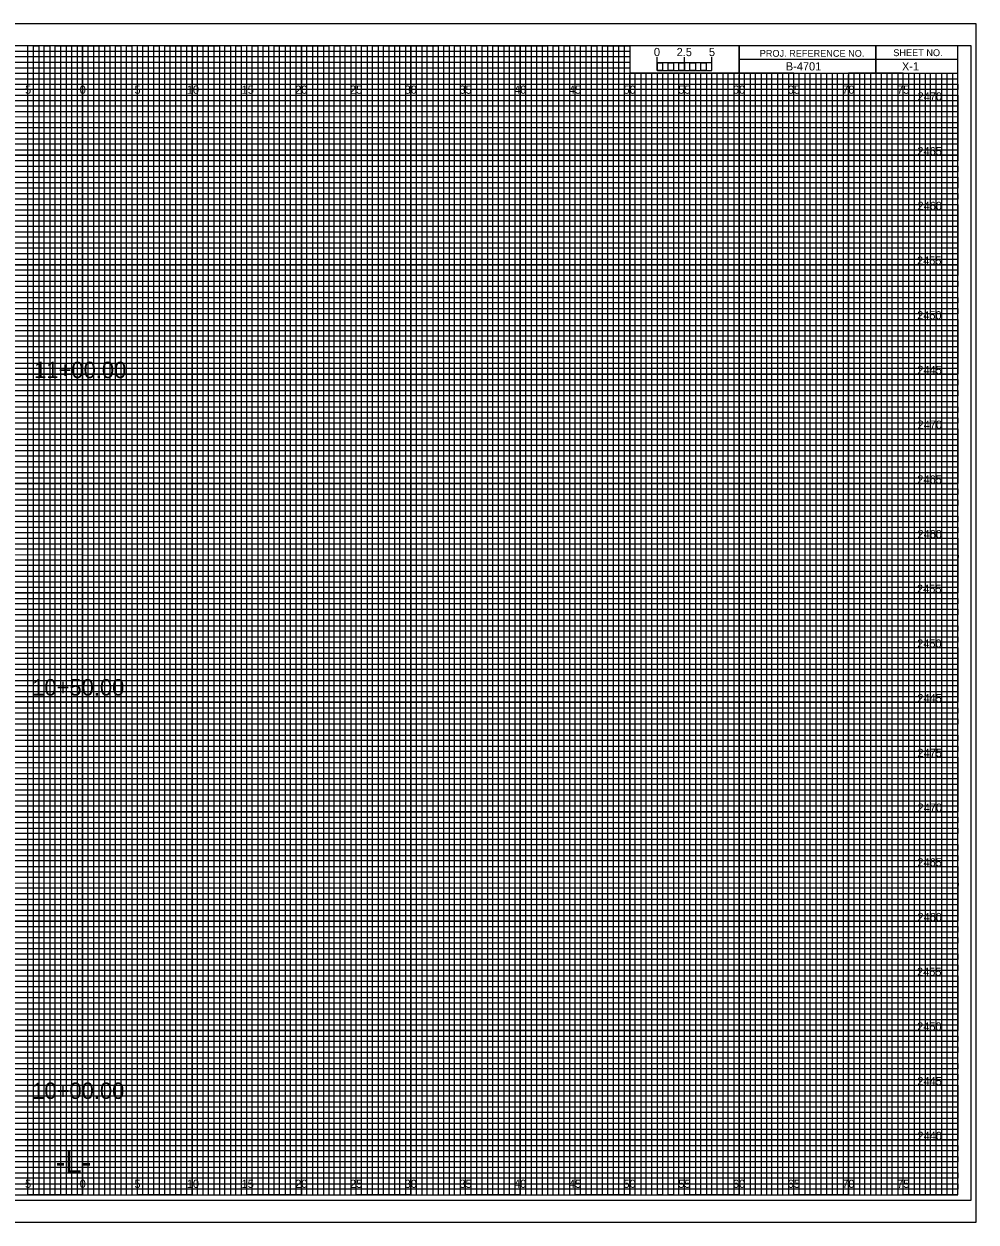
# Model space of a CAD drawing. Extents: x -7 to 162, y -2 to 107.
# Drawn here: x 74.6 to 161.7, y -2.5 to 107 of the extents above; entities that cross this region are included whole.
import ezdxf

# ---------------------------------------------------------------- set-up
doc = ezdxf.new("R2010")
doc.units = 0
for name, color, linetype in [('Exist CMT Pavement', 7, 'Continuous'), ('Exist Cross Section Cell', 7, 'Continuous'), ('Exist XS Ground Line', 7, 'Continuous'), ('Prop CMT Pvmt Course 1 Wedge', 7, 'Continuous'), ('Prop CMT Pvmt Surface', 7, 'Continuous'), ('Prop CMT Pvmt Surface Shoulder', 7, 'Continuous'), ('Prop CMT Pvmt Wedge Surface 1', 7, 'Continuous'), ('Prop CMT Pvmt Wedge Surface 2', 7, 'Continuous'), ('Prop CMT Pvmt Wedge Surface 3', 7, 'Continuous'), ('Prop CMT Shld Paved Course 1', 7, 'Continuous'), ('Prop CMT Shld Paved Course 2', 7, 'Continuous'), ('Prop CMT Shld Paved Course 3', 7, 'Continuous'), ('Prop CMT Slope Grass', 7, 'Continuous'), ('Prop CMT Subgrade Earthwork', 7, 'Continuous'), ('Prop XS EOT Tick Mark', 7, 'Continuous'), ('Scratch_Level_0', 7, 'Continuous'), ('Scratch_Level_1', 7, 'Continuous')]:
    doc.layers.add(name, color=color, linetype=linetype)

msp = doc.modelspace()

# ---------------------------------------------------------------- linework, layer by layer
at = {"layer": 'Exist XS Ground Line'}
for p, q in [((75, 105), (70, 105)), ((75, 0), (75, 105)), ((85, 105), (80, 105)), ((80, 105), (80, 0)), ((85, 0), (85, 105)), ((95, 105), (90, 105)), ((90, 105), (90, 0)), ((95, 0), (95, 105)), ((105, 105), (100, 105)), ((100, 105), (100, 0)), ((105, 0), (105, 105)), ((115, 105), (110, 105)), ((110, 105), (110, 0)), ((115, 0), (115, 105)), ((125, 105), (120, 105)), ((120, 105), (120, 0)), ((125, 0), (125, 105)), ((130, 105), (130, 0)), ((135, 0), (135, 102.5)), ((145, 102.5), (140, 102.5)), ((140, 102.5), (140, 0)), ((145, 0), (145, 102.5)), ((155, 102.5), (150, 102.5)), ((150, 102.5), (150, 0)), ((155, 0), (155, 102.5)), ((80, 0), (75, 0)), ((90, 0), (85, 0)), ((100, 0), (95, 0)), ((110, 0), (105, 0)), ((120, 0), (115, 0)), ((130, 0), (125, 0)), ((140, 0), (135, 0)), ((150, 0), (145, 0)), ((160, 0), (155, 0)), ((160, 0), (160, 0))]:
    msp.add_line(p, q, dxfattribs=at)
for points in [[(0, 100), (160, 100), (160, 95), (0, 95)], [(0, 90), (160, 90), (160, 85), (0, 85)], [(0, 80), (160, 80), (160, 75), (0, 75)], [(0, 70), (160, 70), (160, 65), (0, 65)], [(0, 60), (160, 60), (160, 55), (0, 55)], [(0, 50), (160, 50), (160, 45), (0, 45)], [(0, 40), (160, 40), (160, 35), (0, 35)], [(0, 30), (160, 30), (160, 25), (0, 25)], [(0, 20), (160, 20), (160, 15), (0, 15)], [(0, 10), (160, 10), (160, 5), (0, 5)]]:
    msp.add_lwpolyline(points, dxfattribs=at)
at = {"layer": 'Prop CMT Pvmt Course 1 Wedge'}
for p, q in [((75, 0), (75, 105)), ((80, 0), (80, 105)), ((85, 0), (85, 105)), ((90, 0), (90, 105)), ((95, 0), (95, 105)), ((100, 0), (100, 105)), ((105, 0), (105, 105)), ((110, 0), (110, 105)), ((115, 0), (115, 105)), ((120, 0), (120, 105)), ((125, 0), (125, 105)), ((130, 0), (130, 102.34)), ((135, 0), (135, 102.34)), ((140, 0), (140, 102.34)), ((145, 0), (145, 102.34)), ((150, 0), (150, 102.34)), ((155, 0), (155, 102.34)), ((0, 100), (160, 100)), ((0, 95), (160, 95)), ((0, 90), (160, 90)), ((0, 85), (160, 85)), ((0, 80), (160, 80)), ((0, 75), (160, 75)), ((0, 70), (160, 70)), ((0, 65), (160, 65)), ((0, 60), (160, 60)), ((0, 55), (160, 55)), ((0, 50), (160, 50)), ((0, 45), (160, 45)), ((0, 40), (160, 40)), ((0, 35), (160, 35)), ((0, 30), (160, 30)), ((0, 25), (160, 25)), ((0, 20), (160, 20)), ((0, 15), (160, 15)), ((0, 10), (160, 10)), ((0, 5), (160, 5))]:
    msp.add_line(p, q, dxfattribs=at)
at = {"layer": 'Prop CMT Shld Paved Course 1'}
for p, q in [((132.5, 102.75), (132.5, 103.95)), ((132.5, 103.45), (132.5, 103.95)), ((135, 102.75), (135, 103.95)), ((137.5, 102.75), (137.5, 103.95)), ((137.5, 103.45), (137.5, 103.95))]:
    msp.add_line(p, q, dxfattribs=at)
for points in [[(137.5, 103.45), (132.5, 103.45), (132.5, 102.75), (137.5, 102.75)], [(132.5, 103.45), (133, 103.45), (133, 102.75), (132.5, 102.75)], [(133.5, 103.45), (134, 103.45), (134, 102.75), (133.5, 102.75)], [(134.5, 103.45), (135, 103.45), (135, 102.75), (134.5, 102.75)], [(135.5, 103.45), (136, 103.45), (136, 102.75), (135.5, 102.75)], [(136.5, 103.45), (137, 103.45), (137, 102.75), (136.5, 102.75)]]:
    msp.add_lwpolyline(points, close=True, dxfattribs=at)
at = {"layer": 'Prop CMT Shld Paved Course 2'}
msp.add_lwpolyline([(-6.7, -2.5), (161.65, -2.5), (161.65, 107), (-6.7, 107)], close=True, dxfattribs=at)
at = {"layer": 'Prop CMT Shld Paved Course 3'}
msp.add_lwpolyline([(-5.4, -0.5), (161.2, -0.5), (161.2, 105), (-5.4, 105)], close=True, dxfattribs=at)
at = {"layer": 'Prop CMT Slope Grass'}
for p, q in [((133.5, 102.5), (133, 102.5)), ((133, 102.5), (133, 0)), ((133.5, 0), (133.5, 102.5)), ((134.5, 102.5), (134, 102.5)), ((134, 102.5), (134, 0)), ((134.5, 0), (134.5, 102.5)), ((133, 0), (132.5, 0)), ((134, 0), (133.5, 0))]:
    msp.add_line(p, q, dxfattribs=at)
for points in [[(75, 0), (75.5, 0), (75.5, 105), (76, 105), (76, 0)], [(76, 0), (76.5, 0), (76.5, 105), (77, 105), (77, 0)], [(77.5, 0), (78, 0), (78, 105), (78.5, 105), (78.5, 0)], [(78.5, 0), (79, 0), (79, 105), (79.5, 105), (79.5, 0)], [(80, 0), (80.5, 0), (80.5, 105), (81, 105), (81, 0)], [(81, 0), (81.5, 0), (81.5, 105), (82, 105), (82, 0)], [(82.5, 0), (83, 0), (83, 105), (83.5, 105), (83.5, 0)], [(83.5, 0), (84, 0), (84, 105), (84.5, 105), (84.5, 0)], [(85, 0), (85.5, 0), (85.5, 105), (86, 105), (86, 0)], [(86, 0), (86.5, 0), (86.5, 105), (87, 105), (87, 0)], [(87.5, 0), (88, 0), (88, 105), (88.5, 105), (88.5, 0)], [(88.5, 0), (89, 0), (89, 105), (89.5, 105), (89.5, 0)], [(90, 0), (90.5, 0), (90.5, 105), (91, 105), (91, 0)], [(91, 0), (91.5, 0), (91.5, 105), (92, 105), (92, 0)], [(92.5, 0), (93, 0), (93, 105), (93.5, 105), (93.5, 0)], [(93.5, 0), (94, 0), (94, 105), (94.5, 105), (94.5, 0)], [(95, 0), (95.5, 0), (95.5, 105), (96, 105), (96, 0)], [(96, 0), (96.5, 0), (96.5, 105), (97, 105), (97, 0)], [(97.5, 0), (98, 0), (98, 105), (98.5, 105), (98.5, 0)], [(98.5, 0), (99, 0), (99, 105), (99.5, 105), (99.5, 0)], [(100, 0), (100.5, 0), (100.5, 105), (101, 105), (101, 0)], [(101, 0), (101.5, 0), (101.5, 105), (102, 105), (102, 0)], [(102.5, 0), (103, 0), (103, 105), (103.5, 105), (103.5, 0)], [(103.5, 0), (104, 0), (104, 105), (104.5, 105), (104.5, 0)], [(105, 0), (105.5, 0), (105.5, 105), (106, 105), (106, 0)], [(106, 0), (106.5, 0), (106.5, 105), (107, 105), (107, 0)], [(107.5, 0), (108, 0), (108, 105), (108.5, 105), (108.5, 0)], [(108.5, 0), (109, 0), (109, 105), (109.5, 105), (109.5, 0)], [(110, 0), (110.5, 0), (110.5, 105), (111, 105), (111, 0)], [(111, 0), (111.5, 0), (111.5, 105), (112, 105), (112, 0)], [(112.5, 0), (113, 0), (113, 105), (113.5, 105), (113.5, 0)], [(113.5, 0), (114, 0), (114, 105), (114.5, 105), (114.5, 0)], [(115, 0), (115.5, 0), (115.5, 105), (116, 105), (116, 0)], [(116, 0), (116.5, 0), (116.5, 105), (117, 105), (117, 0)], [(117.5, 0), (118, 0), (118, 105), (118.5, 105), (118.5, 0)], [(118.5, 0), (119, 0), (119, 105), (119.5, 105), (119.5, 0)], [(120, 0), (120.5, 0), (120.5, 105), (121, 105), (121, 0)], [(121, 0), (121.5, 0), (121.5, 105), (122, 105), (122, 0)], [(122.5, 0), (123, 0), (123, 105), (123.5, 105), (123.5, 0)], [(123.5, 0), (124, 0), (124, 105), (124.5, 105), (124.5, 0)], [(125, 0), (125.5, 0), (125.5, 105), (126, 105), (126, 0)], [(126, 0), (126.5, 0), (126.5, 105), (127, 105), (127, 0)], [(127.5, 0), (128, 0), (128, 105), (128.5, 105), (128.5, 0)], [(128.5, 0), (129, 0), (129, 105), (129.5, 105), (129.5, 0)], [(130, 0), (130.5, 0), (130.5, 102.5), (131.01, 102.5), (131.01, 0)], [(131, 0), (131.5, 0), (131.5, 102.5), (132, 102.5), (132, 0)], [(135, 0), (135.49, 0), (135.49, 102.5), (136, 102.5), (136, 0)], [(136, 0), (136.5, 0), (136.5, 102.5), (137.03, 102.5), (137.03, 0)], [(137.5, 0), (138, 0), (138, 102.5), (138.5, 102.5), (138.5, 0)], [(138.5, 0), (139, 0), (139, 102.5), (139.5, 102.5), (139.5, 0)], [(140, 0), (140.5, 0), (140.5, 102.5), (141, 102.5), (141, 0)], [(141, 0), (141.5, 0), (141.5, 102.5), (142, 102.5), (142, 0)], [(142.5, 0), (143, 0), (143, 102.5), (143.5, 102.5), (143.5, 0)], [(143.5, 0), (144, 0), (144, 102.5), (144.5, 102.5), (144.5, 0)], [(145, 0), (145.5, 0), (145.5, 102.5), (146, 102.5), (146, 0)], [(146, 0), (146.5, 0), (146.5, 102.5), (147, 102.5), (147, 0)], [(147.5, 0), (148, 0), (148, 102.5), (148.5, 102.5), (148.5, 0)], [(148.5, 0), (149, 0), (149, 102.5), (149.5, 102.5), (149.5, 0)], [(150, 0), (150.5, 0), (150.5, 102.5), (151, 102.5), (151, 0)], [(151, 0), (151.5, 0), (151.5, 102.5), (152, 102.5), (152, 0)], [(152.5, 0), (153, 0), (153, 102.5), (153.5, 102.5), (153.5, 0)], [(153.5, 0), (154, 0), (154, 102.5), (154.5, 102.5), (154.5, 0)], [(155, 0), (155.5, 0), (155.5, 102.5), (156, 102.5), (156, 0)], [(156, 0), (156.5, 0), (156.5, 102.5), (157, 102.5), (157, 0)], [(157.5, 0), (158, 0), (158, 102.5), (158.5, 102.5), (158.5, 0)], [(158.5, 0), (159, 0), (159, 102.5), (159.5, 102.5), (159.5, 0)]]:
    msp.add_lwpolyline(points, dxfattribs=at)
at = {"layer": 'Prop CMT Subgrade Earthwork'}
for p, q in [((161.65, 107), (-6.7, 107)), ((-6.7, -2.5), (161.65, -2.5))]:
    msp.add_line(p, q, dxfattribs=at)
at = {"layer": 'Prop XS EOT Tick Mark'}
for p, q in [((152.5, 105), (152.5, 102.5)), ((152.5, 102.5), (152.5, 105)), ((160, 103.75), (140, 103.75)), ((140, 103.75), (140, 102.5)), ((140, 102.5), (160, 102.5))]:
    msp.add_line(p, q, dxfattribs=at)
for points in [[(160, 105), (0, 105), (0, 0), (160, 0)], [(140, 105), (130, 105), (130, 102.52), (140, 102.52)], [(160, 105), (140, 105), (140, 102.5), (160, 102.5)]]:
    msp.add_lwpolyline(points, close=True, dxfattribs=at)
at = {"layer": 'Scratch_Level_0'}
for points in [[(72.5, 0), (77.5, 0), (77.5, 105), (82.5, 105), (82.5, 0), (87.5, 0), (87.5, 105), (92.5, 105), (92.5, 0), (97.5, 0), (97.5, 105), (102.5, 105), (102.5, 0), (107.5, 0), (107.5, 105), (112.5, 105), (112.5, 0), (117.5, 0), (117.5, 105), (122.5, 105), (122.5, 0), (127.5, 0), (127.5, 105), (129.97, 105), (130, 105), (130, 102.5), (132.5, 102.5), (132.5, 0), (137.5, 0), (137.5, 102.5), (142.5, 102.5), (142.5, 0), (147.5, 0), (147.5, 102.5), (152.5, 102.5), (152.5, 0), (157.5, 0), (157.5, 102.5)], [(0, 102.5), (137.5, 102.5)], [(0, 92.5), (160, 92.5), (160, 97.5), (0, 97.5)], [(0, 82.5), (160, 82.5), (160, 87.5), (0, 87.5)], [(0, 72.5), (160, 72.5), (160, 77.5), (0, 77.5)], [(0, 62.5), (160, 62.5), (160, 67.5), (0, 67.5)], [(0, 52.5), (160, 52.5), (160, 57.5), (0, 57.5)], [(0, 42.5), (160, 42.5), (160, 47.5), (0, 47.5)], [(0, 32.5), (160, 32.5), (160, 37.5), (0, 37.5)], [(0, 22.5), (160, 22.5), (160, 27.5), (0, 27.5)], [(0, 12.5), (160, 12.5), (160, 17.5), (0, 17.5)], [(0, 2.5), (160, 2.5), (160, 7.5), (0, 7.5)]]:
    msp.add_lwpolyline(points, dxfattribs=at)
at = {"layer": 'Scratch_Level_1'}
for p, q in [((0, 104.5), (130, 104.5)), ((130, 104.5), (130, 103.99)), ((130, 103.99), (0, 103.99)), ((0, 103.5), (130, 103.5)), ((130, 102.95), (0, 102.95)), ((130, 103.5), (130, 102.95)), ((0, 102), (160, 102))]:
    msp.add_line(p, q, dxfattribs=at)
for points in [[(0, 101.5), (135, 101.5), (160, 101.5), (160, 101), (0, 101)], [(0, 100.5), (160, 100.5), (160, 99.5), (0, 99.5)], [(0, 99), (160, 99), (160, 98.5), (0, 98.49)], [(0, 98), (160, 98), (160, 97), (0, 97)], [(0, 96.5), (160, 96.5), (160, 96), (0, 96)], [(0, 95.5), (160, 95.5), (160, 94.5), (0, 94.5)], [(0, 94), (160, 94), (160, 93.5), (0, 93.5)], [(0, 93), (160, 93), (160, 92), (0, 92)], [(0, 91.5), (160, 91.5), (160, 91), (0, 91)], [(0, 90.5), (160, 90.5), (160, 89.5), (0, 89.5)], [(0, 89), (160, 89), (160, 88.5), (0, 88.5)], [(0, 88), (160, 88), (160, 86.98), (160, 86.5), (160, 86), (0, 86)], [(0, 87), (160, 87), (160, 86.5), (0, 86.5)], [(0, 85.5), (160, 85.5), (160, 84.5), (0, 84.52)], [(0, 84.52), (160, 84.5), (160, 84), (0, 84)], [(0, 83.5), (160, 83.5), (160, 83), (0, 83)], [(0, 82), (160, 82), (160, 81.5), (0, 81.5)], [(0, 81), (160, 81), (160, 80.5), (0, 80.5)], [(-0.04, 79.45), (160, 79.45), (160, 78.94), (-0.04, 78.94)], [(0, 78.5), (160, 78.5), (160, 78), (0, 78)], [(0, 77), (160, 77), (160, 76.5), (0, 76.5)], [(0, 76), (160, 76), (160, 75.5), (0, 75.5)], [(0, 74.5), (160, 74.5), (160, 74), (0, 74)], [(0, 73.5), (160, 73.5), (160, 73), (0, 73)], [(0, 72), (160, 72), (160, 71.5), (0, 71.5)], [(0, 71), (160, 71), (160, 70.5), (0, 70.5)], [(0, 69.5), (160, 69.5), (160, 68.99), (0, 69)], [(0, 68.5), (160, 68.5), (160, 68), (0, 68)], [(0, 67), (160, 67), (160, 66.5), (0, 66.5)], [(0, 66), (160, 66), (160, 65.5), (0, 65.5)], [(0, 64.5), (160, 64.5), (160, 64), (0, 64)], [(0, 63.5), (160, 63.5), (160, 63), (0, 63)], [(0, 62), (160, 62), (160, 61.5), (0, 61.5)], [(0, 61), (160, 61), (160, 60.5), (0, 60.5)], [(0, 59.5), (160, 59.5), (160, 59), (0, 59)], [(0, 58.5), (160.03, 58.45), (160, 58), (0, 58)], [(0, 57), (160, 57), (160, 56.5), (0, 56.5)], [(0, 56), (160, 56), (160, 55.5), (0, 55.5)], [(0, 54.5), (160, 54.5), (160, 54), (0, 54)], [(0, 53.5), (160, 53.5), (160, 53), (0, 53)], [(0, 52), (160, 52), (160, 51.5), (0, 51.5)], [(0, 51), (160, 51), (160, 50.5), (0, 50.5)], [(0, 49.5), (160, 49.5), (160, 49), (0, 49)], [(0, 48.5), (160, 48.5), (160, 48), (0, 48)], [(0, 47), (160, 47), (160, 46.5), (0, 46.5)], [(0, 46), (160, 46), (160, 45.5), (0, 45.5)], [(0, 44.5), (160, 44.5), (160, 44), (0, 44)], [(0, 43.5), (160, 43.5), (160, 43), (0, 43)], [(0, 42), (160, 42), (160, 41.5), (0, 41.5)], [(0, 41), (160, 41), (160, 40.5), (0, 40.5)], [(0, 39.5), (160, 39.5), (160, 38.99), (0, 39)], [(0, 38.5), (160, 38.5), (160, 38), (0, 38)], [(0, 37), (160, 37), (160, 36.5), (0, 36.5)], [(0, 36), (160, 36), (160, 35.5), (0, 35.5)], [(0, 34.5), (160, 34.5), (160, 34), (0, 34)], [(0, 33.5), (160, 33.5), (160, 33), (0, 33)], [(0, 32), (160, 32), (160, 31.5), (0, 31.5)], [(0, 31), (160, 31), (160, 30.5), (0, 30.5)], [(0, 29.5), (160, 29.5), (160, 29), (0, 29)], [(0, 28.5), (160.03, 28.46), (160, 28), (0, 28)], [(0, 27), (160, 27), (160, 26.5), (0, 26.5)], [(0, 26), (160, 26), (160, 25.5), (0, 25.5)], [(0, 24.5), (160, 24.5), (160, 24), (0, 24)], [(0, 23.5), (160, 23.5), (160, 23), (0, 23)], [(0, 22), (160, 22), (160, 21.5), (0, 21.5)], [(0, 21), (160, 21), (160, 20.5), (0, 20.5)], [(0, 19.5), (160, 19.5), (160, 19), (0, 19)], [(0, 18.5), (160, 18.5), (160, 18), (0, 18)], [(0, 17), (160, 17), (160, 16.5), (0, 16.5)], [(0, 16), (160, 16), (160, 15.5), (0, 15.5)], [(0, 14.5), (160, 14.5), (160, 14), (0, 14)], [(0, 13.5), (160, 13.5), (160, 13), (0, 13)], [(0, 12), (160, 12), (160, 11.5), (0, 11.5)], [(0, 11), (160, 11), (160, 10.5), (0, 10.5)], [(0, 9.5), (160, 9.5), (160, 9), (0, 9)], [(0, 8.5), (160, 8.5), (160, 8), (0, 8)], [(0, 7), (160, 7), (160, 6.5), (0, 6.5)], [(0, 6), (160, 6), (160, 5.5), (0, 5.5)], [(0, 4.5), (160, 4.5), (160, 4), (0, 4)], [(0, 3.5), (160, 3.5), (160, 3), (0, 3)], [(0, 2), (160, 2), (160, 1.5), (0, 1.5)], [(0, 1), (160, 1), (160, 0.5), (0, 0.5)]]:
    msp.add_lwpolyline(points, dxfattribs=at)

# ---------------------------------------------------------------- texts
at = {"layer": 'Exist CMT Pavement'}
for s, p in [('11+00.00', (75.57, 74.63)), ('10+50.00', (75.39, 45.62)), ('10+00.00', (75.39, 8.75))]:
    msp.add_text(s, height=1.5, dxfattribs=at).set_placement(p)
at = {"layer": 'Exist Cross Section Cell'}
for s, p in [('5', (74.74, 100.62)), ('0', (79.73, 100.62)), ('0', (79.73, 100.62)), ('5', (84.74, 100.62)), ('10', (89.52, 100.62)), ('15', (94.53, 100.62)), ('20', (99.43, 100.62)), ('25', (104.44, 100.62)), ('30', (109.43, 100.62)), ('35', (114.44, 100.62)), ('40', (119.43, 100.62)), ('45', (124.44, 100.62)), ('50', (129.43, 100.62)), ('55', (134.44, 100.62)), ('60', (139.43, 100.62)), ('65', (144.44, 100.62)), ('70', (149.43, 100.62)), ('75', (154.44, 100.62)), ('5', (74.74, 0.62)), ('0', (79.73, 0.62)), ('0', (79.73, 0.62)), ('5', (84.74, 0.62)), ('10', (89.52, 0.62)), ('15', (94.53, 0.62)), ('20', (99.43, 0.62)), ('25', (104.44, 0.62)), ('30', (109.43, 0.62)), ('35', (114.44, 0.62)), ('40', (119.43, 0.62)), ('45', (124.44, 0.62)), ('50', (129.43, 0.62)), ('55', (134.44, 0.62)), ('60', (139.43, 0.62)), ('65', (144.44, 0.62)), ('70', (149.43, 0.62)), ('75', (154.44, 0.62))]:
    msp.add_text(s, height=0.75, dxfattribs=at).set_placement(p)
at = {"layer": 'Prop CMT Pvmt Surface'}
for s, p in [('2470', (156.31, 100)), ('2465', (156.29, 95)), ('2460', (156.3, 90)), ('2455', (156.26, 85)), ('2450', (156.27, 80)), ('2445', (156.29, 75)), ('2470', (156.31, 70)), ('2465', (156.29, 65)), ('2460', (156.3, 60)), ('2455', (156.26, 55)), ('2450', (156.27, 50)), ('2445', (156.29, 45)), ('2475', (156.3, 40)), ('2470', (156.31, 35)), ('2465', (156.29, 30)), ('2460', (156.3, 25)), ('2455', (156.26, 20)), ('2450', (156.27, 15)), ('2445', (156.29, 10)), ('2440', (156.3, 5))]:
    msp.add_text(s, height=0.75, dxfattribs=at).set_placement(p)
at = {"layer": 'Prop CMT Pvmt Surface Shoulder'}
for s, p in [('2.5', (134.29, 104.06)), ('5', (137.24, 104.06))]:
    msp.add_text(s, height=0.75, dxfattribs=at).set_placement(p)
at = {"layer": 'Prop CMT Pvmt Wedge Surface 1'}
msp.add_text('X-1', height=0.75, dxfattribs=at).set_placement((154.88, 102.75))
at = {"layer": 'Prop CMT Pvmt Wedge Surface 2'}
msp.add_text('B-4701', height=0.75, dxfattribs=at).set_placement((144.27, 102.75))
at = {"layer": 'Prop CMT Pvmt Wedge Surface 3'}
msp.add_text('-L-', height=2, dxfattribs=at).set_placement((77.53, 2))
at = {"layer": 'Prop CMT Shld Paved Course 1'}
msp.add_text('0', height=0.75, dxfattribs=at).set_placement((132.21, 104.06))
at = {"layer": 'Prop XS EOT Tick Mark'}
for s, p in [('PROJ. REFERENCE NO.', (141.88, 104)), ('SHEET NO.', (154.09, 104.06))]:
    msp.add_text(s, height=0.625, dxfattribs=at).set_placement(p)

doc.saveas('drawing.dxf')
